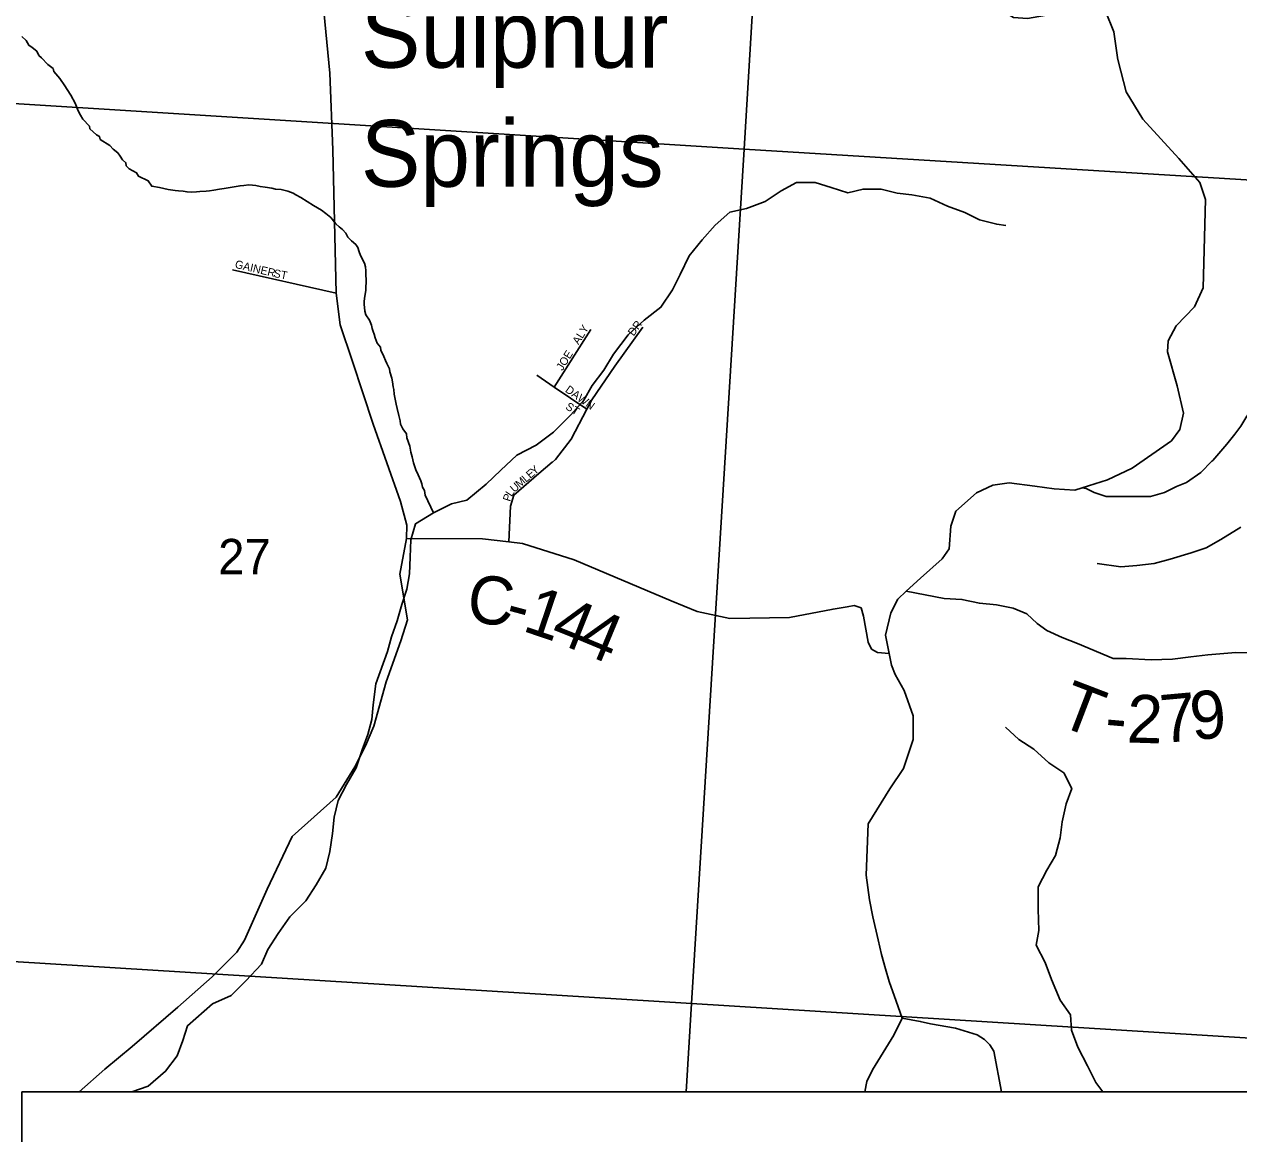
# Model space of a CAD drawing. Extents: x 0 to 34, y 0 to 22.
# Drawn here: x 6.056 to 7.493, y 16.725 to 18.037 of the extents above; entities that cross this region are included whole.
import ezdxf

# ---------------------------------------------------------------- set-up
doc = ezdxf.new("R2010")
doc.units = 0
for name, color, linetype in [('GM_X_County_Road', 7, 'Continuous'), ('GM_X_County_Road_Text', 7, 'Continuous'), ('GM_X_Minor_River', 7, 'Continuous'), ('GM_X_Section', 7, 'Continuous'), ('GM_X_Section_Text', 7, 'Continuous'), ('GM_X_Township_Road', 7, 'Continuous'), ('GM_X_Township_Road_Text', 7, 'Continuous'), ('GM_X_Township_ROW', 7, 'Continuous'), ('GM_X_Township_Subdivision', 7, 'Continuous'), ('GM_X_Township_Subdivision_Text', 7, 'Continuous'), ('GM_X_Unincorporated_Text', 7, 'Continuous'), ('SH_Text', 7, 'Continuous')]:
    doc.layers.add(name, color=color, linetype=linetype)

msp = doc.modelspace()

# ---------------------------------------------------------------- linework, layer by layer
at = {"layer": 'GM_X_County_Road'}
for points in [[(7.3497, 17.9972), (7.3496, 17.9977), (7.3453, 18.028), (7.3354, 18.0523), (7.3241, 18.058), (7.243, 18.0436), (7.2267, 18.0451), (7.207, 18.0569), (7.1646, 18.1101), (7.1517, 18.1188), (7.126, 18.1314), (7.0809, 18.1546), (7.0506, 18.18), (6.9559, 18.313), (6.904, 18.3931), (6.865, 18.4619), (6.8533, 18.4858), (6.8431, 18.5151), (6.8389, 18.5481), (6.8321, 18.5724)], [(6.121, 16.7743), (6.1517, 16.8012), (6.1839, 16.8279), (6.2381, 16.8746), (6.2786, 16.9103), (6.3078, 16.9395), (6.3166, 16.9535), (6.3435, 17.014), (6.3732, 17.0763), (6.4251, 17.1227), (6.4472, 17.1586), (6.4599, 17.1835), (6.4699, 17.2067), (6.4842, 17.2592), (6.5019, 17.3079), (6.5095, 17.3327), (6.5006, 17.3866), (6.5085, 17.4288), (6.5089, 17.4447), (6.5013, 17.4725), (6.4688, 17.5641), (6.4445, 17.6379), (6.4298, 17.6816), (6.4252, 17.7188), (6.4214, 17.8884), (6.4177, 17.9792), (6.4082, 18.0772)], [(7.0794, 17.2927), (7.0752, 17.3145), (7.0816, 17.3407), (7.0896, 17.3571), (7.0997, 17.3663), (7.1165, 17.3818), (7.1422, 17.4046), (7.1506, 17.4164), (7.1525, 17.4434), (7.1582, 17.4609), (7.1828, 17.4829), (7.2021, 17.492), (7.2214, 17.4947), (7.2517, 17.4905), (7.2748, 17.4875), (7.2991, 17.4859), (7.3077, 17.4886), (7.3377, 17.4981), (7.3669, 17.5121), (7.4134, 17.5441), (7.4233, 17.5578), (7.4278, 17.5771), (7.4203, 17.6091), (7.4089, 17.6494), (7.4093, 17.6627), (7.4191, 17.6802), (7.4407, 17.7026), (7.4509, 17.725), (7.4536, 17.8296), (7.4468, 17.8497), (7.4222, 17.8782), (7.3794, 17.9246), (7.36, 17.9569), (7.3502, 17.9938), (7.3497, 17.9972)], [(6.5085, 17.4288), (6.5985, 17.4285), (6.6294, 17.4248), (6.6456, 17.4229), (6.7066, 17.4035), (6.8217, 17.3549), (6.8522, 17.3424), (6.891, 17.3341), (6.9617, 17.3354), (7.013, 17.3452), (7.0296, 17.3479), (7.0379, 17.3493), (7.0462, 17.3466), (7.049, 17.3369), (7.0546, 17.3063), (7.0587, 17.298), (7.0657, 17.2938), (7.0794, 17.2927)], [(7.0949, 16.8616), (7.0879, 16.8817), (7.0796, 16.9048), (7.0749, 16.9197), (7.0705, 16.9366), (7.0663, 16.954), (7.0603, 16.9811), (7.0563, 17.0014), (7.0521, 17.0306), (7.0544, 17.0913), (7.0801, 17.1327), (7.0964, 17.1567), (7.1078, 17.1909), (7.1078, 17.219), (7.0972, 17.2491), (7.0866, 17.2677), (7.082, 17.2791), (7.0794, 17.2927)], [(7.0507, 16.7743), (7.0532, 16.7864), (7.0599, 16.8004), (7.0851, 16.8413), (7.0949, 16.8616)], [(7.0949, 16.8616), (7.1163, 16.8577), (7.1285, 16.8546), (7.1579, 16.8496), (7.1834, 16.8416), (7.1923, 16.8361), (7.1985, 16.8301), (7.2032, 16.8226), (7.2125, 16.7743)]]:
    msp.add_lwpolyline(points, dxfattribs=at)
at = {"layer": 'GM_X_Minor_River'}
for points in [[(6.1767, 17.8694), (6.1764, 17.8732), (6.1723, 17.8764), (6.1697, 17.881), (6.1668, 17.8848), (6.1616, 17.8891), (6.1575, 17.8937), (6.1462, 17.9007), (6.1452, 17.9042), (6.1418, 17.9061), (6.1339, 17.9131), (6.1333, 17.9165), (6.1254, 17.9247), (6.1229, 17.9293), (6.1199, 17.9346), (6.1163, 17.9434), (6.1112, 17.953), (6.1071, 17.9596), (6.1042, 17.9642), (6.0982, 17.9726), (6.0912, 17.9811), (6.0905, 17.9845), (6.0841, 17.9892), (6.0767, 17.9973), (6.0734, 18), (6.0712, 18.005), (6.0656, 18.0093), (6.0618, 18.012), (6.0585, 18.0178), (6.0533, 18.0224)], [(6.5404, 17.4591), (6.5305, 17.4798), (6.5299, 17.4855), (6.5273, 17.4894), (6.5266, 17.4932), (6.5252, 17.497), (6.5222, 17.5039), (6.5193, 17.51), (6.5168, 17.5184), (6.515, 17.5253), (6.5136, 17.531), (6.5122, 17.5379), (6.509, 17.5479), (6.5083, 17.5524), (6.5039, 17.5586), (6.5013, 17.564), (6.501, 17.5678), (6.4992, 17.5743), (6.4975, 17.5823), (6.4964, 17.5876), (6.495, 17.5934), (6.494, 17.5995), (6.4933, 17.6048), (6.4926, 17.6082), (6.492, 17.6139), (6.4909, 17.6185), (6.4888, 17.6258), (6.4884, 17.6292), (6.4851, 17.6357), (6.4837, 17.6392), (6.4815, 17.6438), (6.4782, 17.6514), (6.4775, 17.6549), (6.4738, 17.6599), (6.4713, 17.666), (6.4702, 17.6702), (6.4691, 17.6737), (6.4677, 17.6771), (6.467, 17.6809), (6.4645, 17.687), (6.4604, 17.6932), (6.459, 17.6974), (6.4583, 17.7058), (6.4584, 17.7096), (6.4593, 17.7153), (6.4605, 17.7221), (6.4608, 17.7358), (6.4604, 17.7392), (6.4605, 17.7453), (6.4599, 17.7499), (6.4588, 17.7544), (6.454, 17.7636), (6.4526, 17.7679), (6.4508, 17.7728), (6.4486, 17.7763), (6.4434, 17.7806), (6.4389, 17.7852), (6.4367, 17.7898), (6.4326, 17.794), (6.4289, 17.7972), (6.4248, 17.801), (6.4188, 17.8083), (6.4129, 17.813), (6.408, 17.8169), (6.3986, 17.8224), (6.3911, 17.8271), (6.3833, 17.8321), (6.3777, 17.8353), (6.3743, 17.8372), (6.3679, 17.8396), (6.3603, 17.8413), (6.3535, 17.8418), (6.349, 17.843), (6.3414, 17.8442), (6.3354, 17.8451), (6.3301, 17.8463), (6.3263, 17.8468), (6.3218, 17.8469), (6.3161, 17.8462), (6.3116, 17.8459), (6.3021, 17.8441), (6.2929, 17.8428), (6.2872, 17.8417), (6.2804, 17.8407), (6.2755, 17.84), (6.2713, 17.8397), (6.2641, 17.8391), (6.2599, 17.8388), (6.2546, 17.8385), (6.2489, 17.8386), (6.2444, 17.8394), (6.2387, 17.8399), (6.2349, 17.8403), (6.2263, 17.8416), (6.2161, 17.8437), (6.207, 17.8454), (6.203, 17.8519), (6.1913, 17.8574), (6.1891, 17.8612), (6.1805, 17.866), (6.1767, 17.8694)], [(6.5028, 17.3505), (6.5089, 17.3687), (6.512, 17.3869), (6.5129, 17.4067), (6.5137, 17.4272), (6.5191, 17.4462), (6.5404, 17.4591), (6.5616, 17.4696), (6.5798, 17.4741), (6.6026, 17.4931), (6.6201, 17.5097), (6.6391, 17.5272), (6.6618, 17.5392), (6.6824, 17.5544), (6.7029, 17.5748), (6.7181, 17.5923), (6.728, 17.6097), (6.7417, 17.6279), (6.7532, 17.6469), (6.7707, 17.6697), (6.7897, 17.6871), (6.8094, 17.7022), (6.8231, 17.7227), (6.8323, 17.7409), (6.843, 17.7629), (6.8582, 17.7819), (6.8734, 17.7993), (6.8909, 17.8145), (6.9106, 17.819), (6.9326, 17.8272), (6.9516, 17.8401), (6.9698, 17.8499), (6.9918, 17.8498), (7.0107, 17.8437), (7.0304, 17.8375), (7.0486, 17.842), (7.0698, 17.842), (7.0887, 17.8373), (7.1061, 17.835), (7.128, 17.8311), (7.1484, 17.8219), (7.1689, 17.8143), (7.1862, 17.8058), (7.2067, 17.8004), (7.2173, 17.7989)], [(7.3255, 17.3992), (7.3535, 17.3953), (7.3724, 17.3968), (7.3929, 17.399), (7.4119, 17.4043), (7.4369, 17.4118), (7.4543, 17.4178), (7.4718, 17.4276), (7.4953, 17.442)], [(6.1836, 16.7743), (6.2029, 16.7812), (6.2234, 16.7986), (6.2371, 16.8168), (6.244, 16.8351), (6.2494, 16.8525), (6.279, 16.8783), (6.301, 16.8881), (6.3185, 16.9055), (6.3368, 16.9252), (6.3444, 16.9427), (6.3566, 16.9616), (6.3703, 16.9813), (6.3893, 17.0003), (6.4015, 17.0193), (6.413, 17.039), (6.4176, 17.0587), (6.4207, 17.08), (6.423, 17.099), (6.4277, 17.1188), (6.4376, 17.1378), (6.449, 17.1575), (6.4559, 17.1787), (6.4628, 17.197), (6.4674, 17.2145), (6.469, 17.2319), (6.4721, 17.257), (6.4859, 17.295), (6.4905, 17.3125), (6.4974, 17.3315), (6.5028, 17.3505)], [(7.2564, 16.9651), (7.2557, 16.9902), (7.2558, 17.0169), (7.2658, 17.0366), (7.2764, 17.054), (7.2818, 17.0746), (7.2842, 17.0936), (7.2888, 17.1149), (7.2957, 17.1331), (7.2859, 17.1514), (7.2685, 17.1636), (7.2504, 17.1797), (7.233, 17.1911), (7.2172, 17.2057)], [(7.3324, 16.7743), (7.3238, 16.7854), (7.3141, 16.8052), (7.3028, 16.8273), (7.2953, 16.8471), (7.2939, 16.8653), (7.2818, 16.8829), (7.2713, 16.9073), (7.2638, 16.9271), (7.2533, 16.9476), (7.2564, 16.9651)]]:
    msp.add_lwpolyline(points, dxfattribs=at)
at = {"layer": 'GM_X_Section'}
for points in [[(5.8561, 18.9573), (6.9681, 18.8952), (6.9079, 17.8893), (5.7907, 17.959)], [(6.9681, 18.8952), (8.0664, 18.8297), (8.012, 17.8219), (6.9079, 17.8893)], [(6.9079, 17.8893), (6.8455, 16.8788), (5.7237, 16.9481), (5.7907, 17.959)], [(8.012, 17.8219), (7.9583, 16.8099), (6.8455, 16.8788), (6.9079, 17.8893)]]:
    msp.add_lwpolyline(points, close=True, dxfattribs=at)
for points in [[(6.795, 16.0591), (6.7831, 15.8661), (5.6567, 15.9275), (5.7237, 16.9481), (6.8455, 16.8788), (6.8391, 16.7743)], [(6.8391, 16.7743), (6.8455, 16.8788), (7.9583, 16.8099), (7.9053, 15.8044), (6.7831, 15.8661), (6.795, 16.0591)]]:
    msp.add_lwpolyline(points, dxfattribs=at)
at = {"layer": 'GM_X_Township_Road'}
msp.add_lwpolyline([(7.5165, 17.2934), (7.4896, 17.2938), (7.4566, 17.2911), (7.4362, 17.2889), (7.4146, 17.2862), (7.3892, 17.2851), (7.3597, 17.287), (7.3445, 17.287), (7.3021, 17.3045), (7.2839, 17.3118), (7.2661, 17.3198), (7.2544, 17.3281), (7.2422, 17.3395), (7.2263, 17.3464), (7.2063, 17.3502), (7.1862, 17.3521), (7.1654, 17.3567), (7.1445, 17.3578), (7.0997, 17.3663)], dxfattribs=at)
at = {"layer": 'GM_X_Township_ROW'}
msp.add_lwpolyline([(7.3077, 17.4886), (7.3126, 17.4878), (7.3221, 17.483), (7.3363, 17.4783), (7.3886, 17.4783), (7.4052, 17.4831), (7.4195, 17.4902), (7.4313, 17.495), (7.448, 17.5069), (7.4612, 17.52), (7.4622, 17.5211), (7.4789, 17.5402), (7.4884, 17.5521), (7.4955, 17.5616), (7.5026, 17.5735), (7.5097, 17.583), (7.5216, 17.5901), (7.5335, 17.5973), (7.5454, 17.602), (7.5644, 17.6044), (7.5747, 17.6044)], dxfattribs=at)
at = {"layer": 'GM_X_Township_Subdivision'}
for points in [[(6.3026, 17.7465), (6.4252, 17.7188)], [(6.6808, 17.519), (6.681, 17.5192), (6.6847, 17.5223), (6.7032, 17.5462), (6.7217, 17.5815), (6.7275, 17.5926), (6.7547, 17.6325), (6.7881, 17.6785)], [(6.6832, 17.6079), (6.7265, 17.676)], [(6.6627, 17.6219), (6.6832, 17.6079), (6.7217, 17.5815)], [(6.6294, 17.4248), (6.6313, 17.4668), (6.6354, 17.4801), (6.665, 17.5055), (6.6808, 17.519)]]:
    msp.add_lwpolyline(points, dxfattribs=at)
at = {"layer": 'SH_Text'}
msp.add_lwpolyline([(6.0532, 16.7743), (7.8426, 16.7743), (7.8426, 16.0591), (6.0532, 16.0591)], close=True, dxfattribs=at)

# ---------------------------------------------------------------- texts
at = {"layer": 'GM_X_County_Road_Text'}
for s, rotation, p in [('C', 353.7827, (6.5784, 17.3304)), ('1', 341.2684, (6.6441, 17.32)), ('-', 344.9773, (6.6225, 17.3258)), ('4', 338.2098, (6.6765, 17.3091)), ('4', 337.4714, (6.7088, 17.2961))]:
    msp.add_text(s, height=0.0568, rotation=rotation, dxfattribs=at).set_placement(p)
at = {"layer": 'GM_X_Section_Text'}
msp.add_text('27', height=0.04186, rotation=0, dxfattribs=at).set_placement((6.2856, 17.3864))
at = {"layer": 'GM_X_Township_Road_Text'}
for s, rotation, p in [('T', 339.0432, (7.2769, 17.2089)), ('2', 358.1514, (7.36, 17.1876)), ('7', 5.1509, (7.4025, 17.1867)), ('9', 6.2418, (7.4386, 17.1899)), ('-', 355.0542, (7.3334, 17.1898))]:
    msp.add_text(s, height=0.0568, rotation=rotation, dxfattribs=at).set_placement(p)
at = {"layer": 'GM_X_Township_Subdivision_Text'}
for s, rotation, p in [('GAINER', 346.7591, (6.3048, 17.749)), ('ST', 348.6904, (6.3506, 17.7381)), ('DR', 53.7428, (6.7771, 17.6674)), ('ALY', 57.9953, (6.712, 17.6573)), ('JOE', 58.2394, (6.6929, 17.6265)), ('DAWN', 324.4621, (6.6954, 17.6028)), ('ST', 327.2652, (6.6957, 17.5825)), ('Y', 40.7109, (6.6599, 17.5033)), ('M', 40.7181, (6.6422, 17.4881)), ('L', 40.7028, (6.6498, 17.4946)), ('E', 40.7192, (6.6549, 17.499)), ('L', 56.1584, (6.6327, 17.4776)), ('U', 41.5169, (6.636, 17.4826)), ('P', 72.0596, (6.631, 17.4718))]:
    msp.add_text(s, height=0.00947, rotation=rotation, dxfattribs=at).set_placement(p)
at = {"layer": 'GM_X_Unincorporated_Text'}
for s, p in [('Sulphur', (6.4544, 17.9855)), ('Springs', (6.4544, 17.8447))]:
    msp.add_text(s, height=0.07898, rotation=0, dxfattribs=at).set_placement(p)

doc.saveas('drawing.dxf')
